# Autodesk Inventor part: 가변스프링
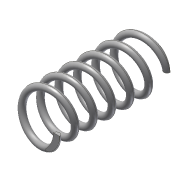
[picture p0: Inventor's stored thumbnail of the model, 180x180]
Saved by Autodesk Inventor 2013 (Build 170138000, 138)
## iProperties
Created: 2020-02
Part Number: 가변스프링
Material: 강철
Document SubType Name: Modeling
Designer: Administrator
Density: 7.85 g/cm^3
Mass: 6.43046 g
Surface Area: 16.6051 cm^2
Volume: 0.819168 cm^3
Author: Administrator
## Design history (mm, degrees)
sketch "스케치1"
  geometry: L1 (0, 0)-(7, 0); L2 (7, 0)-(7, 35.5); L3 (7, 35.5)-(0, 35.5); L4 (0, 35.5)-(0, 0); C1 r 1 at (7, 0)
  constraints: 8 end point, 2 parallel, 1 centre point, 1 coincident, 1 horizontal, 1 perpendicular
  dimensions: "d0" = 14 diameter of L2 L4; "d2" = 35.5 distance of L1.end L2.end (derived); "d3" = 2 diameter of C1
feature "코일1" pitch "d4" = 10; turns "d6" = 6; dims "d5" = 35.5 (= d2), "d7" = 0, angle "d8" = 90 deg, angle "d9" = 90 deg, "d10" = 0, "d11" = 0
sketch "스케치2"
  geometry: L1 (-8, 0)-(-6, 0) reference; 1 further point
  constraints: 1 horizontal alignment
extrude "돌출1" cut sketch "스케치2" stored distance "d12" = 10; taper "d13" = 0 deg
node "작업 평면1"
sketch "스케치3"
  geometry: L1 (1, 0)-(-1, 0) reference; 1 further point
  constraints: 1 horizontal alignment
extrude "돌출2" cut sketch "스케치3" stored distance "d15" = 10; taper "d16" = 0 deg
node "솔리드1"
node "절단 모서리 투영1"
node "절단 모서리 투영2"
other parameters: "d14" = 90 deg
